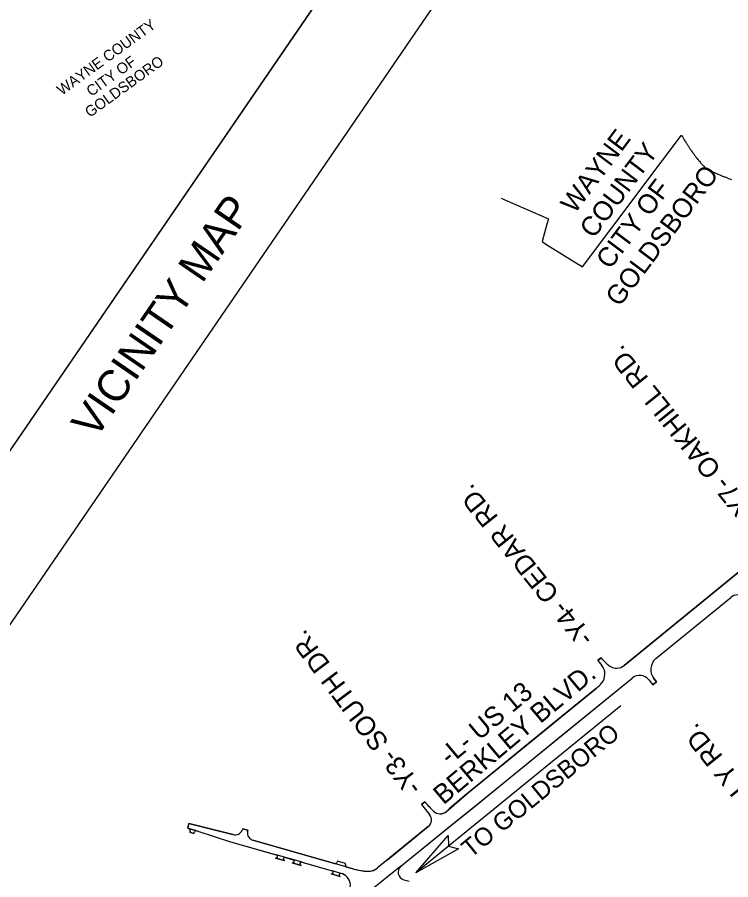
# Model space of a CAD drawing. Extents: x 2312641 to 2338852, y 590461 to 618614.
# Drawn here: x 2320204 to 2323527, y 598163 to 602179 of the extents above; entities that cross this region are included whole.
import ezdxf

# ---------------------------------------------------------------- set-up
doc = ezdxf.new("R2010")
doc.units = 0
for name, color, linetype in [('Default', 7, 'Continuous'), ('Default Symbol CELL', 7, 'Continuous'), ('Exist Property Iron Pin Cogo Number', 7, 'Continuous'), ('Exist Property Monument CELL', 7, 'Continuous'), ('Exist Property Monument Cogo Elevation', 7, 'Continuous'), ('Exist Property Monument Cogo Number', 7, 'Continuous'), ('Exist Structure Minor Pipes RCP 15 Inch Text', 7, 'Continuous'), ('Exist Utilities Power Pole Text', 7, 'Continuous')]:
    doc.layers.add(name, color=color, linetype=linetype)

msp = doc.modelspace()

# ---------------------------------------------------------------- linework, layer by layer
at = {"layer": 'Default'}
for points in [[(2322457, 601336.8), (2322500, 601317.9), (2322677.8, 601240.9), (2322670.8, 601214.8), (2322649.2, 601134.8), (2322665.8, 601122.3), (2322836, 601016.4), (2323109.5, 601379.8), (2323113.5, 601384.9), (2323297, 601629.1), (2323299.2, 601626), (2323301.8, 601622.5), (2323303.2, 601620), (2323305, 601617.6), (2323307.2, 601614.2), (2323309, 601611.6), (2323310.8, 601608.6), (2323313.5, 601603.9), (2323315.5, 601600.4), (2323317.8, 601596.4), (2323320.8, 601591.9), (2323322.2, 601589.4), (2323324, 601586.9), (2323325.5, 601584.4), (2323327.5, 601581.5), (2323329.8, 601577.8), (2323331.5, 601575.2), (2323333.8, 601571.8), (2323335.2, 601569.3), (2323337.2, 601566.4), (2323339.2, 601563.5), (2323341.5, 601560.2), (2323343.8, 601556.9), (2323346.8, 601552.6), (2323349.5, 601548.8), (2323352, 601545.6), (2323354.5, 601542.4), (2323356.2, 601540.1), (2323358.5, 601537.3), (2323360.8, 601534.1), (2323363, 601531.2), (2323365.2, 601528), (2323367.8, 601524.8), (2323369.8, 601522), (2323372.5, 601518.6), (2323374.5, 601516.2), (2323376.5, 601513.9), (2323379, 601510.9), (2323381.5, 601508.1), (2323384.2, 601504.8), (2323386.8, 601501.7), (2323389.2, 601498.6), (2323393, 601494.2), (2323395.8, 601490.9), (2323398.2, 601487.9), (2323401, 601484.9), (2323404, 601481.5), (2323406.5, 601479.1), (2323409.5, 601476.6), (2323412.8, 601474.1), (2323415.8, 601471.6), (2323418.5, 601469.8), (2323422.8, 601467.8), (2323426.5, 601466.1), (2323430, 601464.5)], [(2323430, 601464.5), (2323434.2, 601462.7), (2323439.2, 601460.6), (2323443, 601459.1), (2323446.8, 601457.6), (2323450.8, 601455.8), (2323454, 601454.4), (2323457.8, 601452.8), (2323460.5, 601451.6), (2323463.8, 601450.1), (2323468, 601448.2), (2323472.2, 601446.3), (2323476, 601444.7), (2323479.8, 601443.1), (2323485.2, 601440.8), (2323489, 601439.3), (2323492.8, 601437.9), (2323496.2, 601436.4), (2323499.8, 601435.1), (2323503.8, 601433.6), (2323507.5, 601432.1), (2323511.2, 601430.7), (2323514, 601429.6), (2323517.2, 601428.4), (2323520.8, 601427.1), (2323526.2, 601424.9), (2323530, 601423.4)]]:
    msp.add_lwpolyline(points, dxfattribs=at)
at = {"layer": 'Default Symbol CELL'}
for p, q in [((2323030.9, 599161), (2323677.4, 599688.8)), ((2323178.7, 599193.2), (2323527, 599477.6)), ((2322907.5, 599183.8), (2322922.9, 599196.5)), ((2322907.5, 599183.8), (2322926.2, 599161)), ((2322922.9, 599196.5), (2322927.1, 599191.4)), ((2322349, 598515.8), (2323067.2, 599102.2)), ((2323146, 599094.2), (2323164.7, 599071.2)), ((2323181.8, 599085), (2323164.7, 599071.2)), ((2323169.3, 599100.4), (2323181.8, 599085.1)), ((2322305.6, 598568.9), (2322901.2, 599055.1)), ((2322203.2, 598480.8), (2322305.6, 598568.9)), ((2322086.7, 598514), (2322102.4, 598526.4)), ((2322086.7, 598514), (2322124.1, 598466.5)), ((2322102.4, 598526.4), (2322102.5, 598526.3)), ((2322231.6, 598422.4), (2322349, 598515.8)), ((2320997.7, 598403.5), (2321003.7, 598424.6)), ((2321003.7, 598424.6), (2321052.1, 598411.9)), ((2321990.8, 598225.9), (2322231.6, 598422.4)), ((2320997.7, 598403.5), (2321045.5, 598388.8)), ((2321045.5, 598388.8), (2321197.7, 598339.2)), ((2321052.1, 598411.9), (2321207.6, 598373.8)), ((2321254.7, 598400.9), (2321251.2, 598392.9)), ((2321254.7, 598400.9), (2321277.9, 598393.9)), ((2321277.9, 598393.9), (2321276.7, 598387.2)), ((2321927.9, 598255.5), (2322118, 598410.7)), ((2321197.7, 598339.2), (2321409.4, 598278.9)), ((2321207.6, 598373.8), (2321209.6, 598373.3)), ((2321301.4, 598347.1), (2321681.6, 598238.7)), ((2321531, 598244.2), (2321409.4, 598278.9)), ((2321529.8, 598244.5), (2321670.6, 598204.4)), ((2321531, 598244.2), (2321670.6, 598204.4)), ((2321771.7, 598213.1), (2321681.6, 598238.7)), ((2321927.9, 598255.5), (2321882.2, 598218.2)), ((2321712.2, 598192.5), (2321670.6, 598204.4))]:
    msp.add_line(p, q, dxfattribs=at)
for centre, radius, start, end in [((2323558.7, 599438.9), 50, 52.6181, 129.228), ((2323058.4, 599299.4), 170, 219.4386, 236.4708), ((2323220.4, 599142.1), 66, 129.228, 219.167), ((2322876.8, 599120.4), 64, 319.4502, 39.4386), ((2322995.4, 599204.4), 56, 236.4708, 309.228), ((2323102.6, 599058.8), 56, 39.167, 129.228), ((2322781, 599202.3), 190, 309.228, 319.4502), ((2322416.6, 598773.9), 400, 218.2482, 226.8574), ((2322092.7, 598441.7), 40, 309.228, 38.2482), ((2322173.8, 598514.9), 45, 226.8574, 310.7078), ((2321219.2, 598406.9), 35, 254.0894, 336.3293), ((2321311, 598380.7), 35, 169.3023, 254.0894), ((2321837.9, 598272.4), 70, 266.286, 309.228), ((2322013.6, 598198), 36, 129.228, 255.684), ((2321696.7, 598134.6), 60, 32.6797, 74.9991), ((2321852.8, 598501.9), 300, 254.3173, 266.286), ((2321703.4, 598138.9), 52, 309.228, 32.6797), ((2324469.9, 607823.5), 9970, 255.68401, 255.82641)]:
    msp.add_arc(centre, radius, start, end, dxfattribs=at)
at = {"layer": 'Exist Property Iron Pin Cogo Number'}
for points in [[(2315736.3, 601363.6), (2318606, 605551.1), (2322182.1, 603100.3), (2319312.3, 598912.9)], [(2322182.1, 603100.3), (2319312.3, 598912.9), (2319691, 598653.4), (2322560.7, 602840.8)]]:
    msp.add_lwpolyline(points, close=True, dxfattribs=at)
at = {"layer": 'Exist Property Monument CELL'}
for p, q in [((2323677.4, 599688.8), (2323030.9, 599161)), ((2323178.7, 599193.2), (2323527, 599477.6)), ((2322908.6, 599184.8), (2322907.5, 599183.8)), ((2322907.5, 599183.8), (2322926.2, 599161)), ((2322922.9, 599196.5), (2322908.6, 599184.8)), ((2322927.1, 599191.4), (2322922.9, 599196.5)), ((2322729.7, 598826.7), (2323067.2, 599102.2)), ((2323146, 599094.2), (2323164.7, 599071.2)), ((2323164.7, 599071.2), (2323181.8, 599085.1)), ((2323181.8, 599085.1), (2323169.3, 599100.4)), ((2322901.2, 599055.1), (2322712.6, 598901.2)), ((2322712.6, 598901.2), (2322286.3, 598553.1)), ((2322329.6, 598500), (2322729.7, 598826.7)), ((2322102.7, 598526), (2322087, 598513.6)), ((2322087, 598513.6), (2322124.1, 598466.5)), ((2322212.2, 598406.6), (2322329.6, 598500)), ((2322217.8, 598494.2), (2322202.7, 598481.2)), ((2322217.8, 598494.2), (2322217.8, 598494.2)), ((2321003.7, 598424.6), (2320997.7, 598403.5)), ((2321052.1, 598411.9), (2321003.7, 598424.6)), ((2320997.7, 598403.5), (2321001.9, 598402.2)), ((2321040.9, 598390.2), (2321001.9, 598402.2)), ((2321001.9, 598402.2), (2321040.9, 598390.2)), ((2321008.6, 598389.9), (2321006.9, 598384.1)), ((2321026.9, 598378.4), (2321006.9, 598384.1)), ((2321006.9, 598384.1), (2321026.9, 598378.4)), ((2321026.9, 598378.4), (2321028.3, 598383.4)), ((2321040.9, 598390.2), (2321045.5, 598388.8)), ((2321045.5, 598388.8), (2321197.7, 598339.2)), ((2321207.6, 598373.8), (2321052.1, 598411.9)), ((2321254.7, 598400.9), (2321251.2, 598392.9)), ((2321277.9, 598393.9), (2321254.7, 598400.9)), ((2321276.7, 598387.2), (2321277.9, 598393.9)), ((2322118, 598410.7), (2321882.2, 598218.2)), ((2321990.8, 598225.9), (2322212.2, 598406.6)), ((2321197.7, 598339.2), (2321411.2, 598278.4)), ((2321209.6, 598373.3), (2321207.6, 598373.8)), ((2321681.6, 598238.7), (2321301.4, 598347.1)), ((2321448.4, 598252.1), (2321407.1, 598263.9)), ((2321407.1, 598263.9), (2321448.4, 598252.1)), ((2321452.5, 598266.6), (2321488.4, 598256.3)), ((2321525.6, 598230.1), (2321484.3, 598241.9)), ((2321484.3, 598241.9), (2321525.6, 598230.1)), ((2321529.8, 598244.5), (2321670.6, 598204.4)), ((2321694.9, 598249.1), (2321693.9, 598245.6)), ((2321733.4, 598238.1), (2321694.9, 598249.1)), ((2321732.4, 598234.6), (2321733.4, 598238.1)), ((2321990.8, 598225.9), (2321839.6, 598105.5)), ((2321707.7, 598178.2), (2321666.1, 598190.1)), ((2321666.9, 598189.9), (2321707.7, 598178.2)), ((2321711.8, 598192.6), (2321711.9, 598192.6))]:
    msp.add_line(p, q, dxfattribs=at)
msp.add_lwpolyline([(2322286.3, 598553.1), (2322286, 598552.9), (2322217.8, 598494.2)], dxfattribs=at)
for centre, radius, start, end in [((2323058.4, 599299.4), 170, 219.4386, 236.4708), ((2323220.4, 599142.1), 66, 129.228, 219.167), ((2322876.8, 599120.4), 64, 319.4502, 39.4386), ((2322995.4, 599204.4), 56, 236.4708, 309.228), ((2323102.6, 599058.8), 56, 39.167, 129.228), ((2322781, 599202.3), 190, 309.228, 319.4502), ((2322416.8, 598773.6), 400, 218.2482, 226.6969), ((2322092.7, 598441.7), 40, 309.228, 38.2482), ((2322173.3, 598515.3), 45, 226.6969, 310.7078), ((2320999, 598392.7), 10, 344.0894, 72.9436), ((2321038, 598380.7), 10, 72.9436, 164.0894), ((2321219.2, 598406.9), 35, 254.0894, 336.3293), ((2321311, 598380.7), 35, 169.3023, 254.0894), ((2321409.1, 598271.1), 7.5, 254.0894, 74.0894), ((2321450.5, 598259.4), 7.5, 74.0894, 254.0894), ((2321486.4, 598249.1), 7.5, 254.0894, 74.0894), ((2321527.7, 598237.3), 7.5, 74.0894, 254.0894), ((2321684.3, 598248.3), 10, 254.0894, 344.0894), ((2321742, 598231.9), 10, 164.0894, 254.124), ((2324469.9, 607823.5), 9982, 254.12399, 254.31727), ((2321837.9, 598272.4), 70, 290.5582, 309.228), ((2322013.6, 598198), 36, 129.228, 255.684), ((2321668.5, 598197.2), 7.5, 257.22, 74.0894), ((2321709.8, 598185.4), 7.5, 74.3889, 253.6632), ((2321694.2, 598132.2), 63, 27.0716, 73.6693), ((2321852.8, 598501.9), 300, 254.3173, 262.8366), ((2321852.8, 598501.9), 300, 262.8366, 266.286), ((2321837.9, 598272.4), 70, 266.286, 290.5582), ((2324469.9, 607823.5), 9970, 255.68401, 255.82641)]:
    msp.add_arc(centre, radius, start, end, dxfattribs=at)
at = {"layer": 'Exist Property Monument Cogo Elevation'}
msp.add_lwpolyline([(2322258.9, 598307.1), (2322060, 598195.1), (2322210.2, 598369), (2322213.1, 598319.8)], close=True, dxfattribs=at)
at = {"layer": 'Exist Property Monument Cogo Number'}
msp.add_lwpolyline([(2321956.1, 602770.5), (2319312.3, 598912.9), (2315736.3, 601363.6), (2318606, 605551.1), (2321083.4, 603853.3), (2320857.4, 603523.5)], dxfattribs=at)
at = {"layer": 'Exist Structure Minor Pipes RCP 15 Inch Text'}
msp.add_line((2323014.3, 598972.4), (2322060, 598195.1), dxfattribs=at)

# ---------------------------------------------------------------- texts
at = {"layer": 'Default'}
for s, height, rotation, p in [('WAYNE COUNTY', 50, 35.8507, (2320411.4, 601813.2)), ('GOLDSBORO', 50, 35.8507, (2320541.8, 601710.1)), ('CITY OF ', 50, 35.8507, (2320548.7, 601807.5)), ('WAYNE', 90, 53.0413, (2322800, 601260.1)), ('COUNTY', 90, 53.0413, (2322888.2, 601144.5)), ('GOLDSBORO', 90, 53.0413, (2323008.5, 600826.3)), ('CITY OF', 90, 53.0413, (2322964.4, 601000.5))]:
    msp.add_text(s, height=height, rotation=rotation, dxfattribs=at).set_placement(p)
at = {"layer": 'Exist Structure Minor Pipes RCP 15 Inch Text'}
for s, height, rotation, p in [('-Y7- OAKHILL RD.', 90, 128.6934, (2323649.2, 599871.4)), ('-Y4- CEDAR RD.', 90, 128.6934, (2322894.9, 599292.4)), ('-Y3- SOUTH DR.', 90, 126.9555, (2322094.9, 598596.8)), ('BERKLEY BLVD.', 90, 39.9635, (2322189, 598509)), ('-L- US 13', 90, 39.9635, (2322217.2, 598692.9)), ('TO GOLDSBORO', 83.325, 39.1657, (2322315.9, 598261.8)), ('-Y5- HOLLY RD.', 90, 128.6934, (2323924.4, 598199.7))]:
    msp.add_text(s, height=height, rotation=rotation, dxfattribs=at).set_placement(p)
at = {"layer": 'Exist Utilities Power Pole Text'}
msp.add_text('VICINITY MAP', height=146.192, rotation=55.5761, dxfattribs=at).set_placement((2320567.9, 600209.7))

doc.saveas('drawing.dxf')
